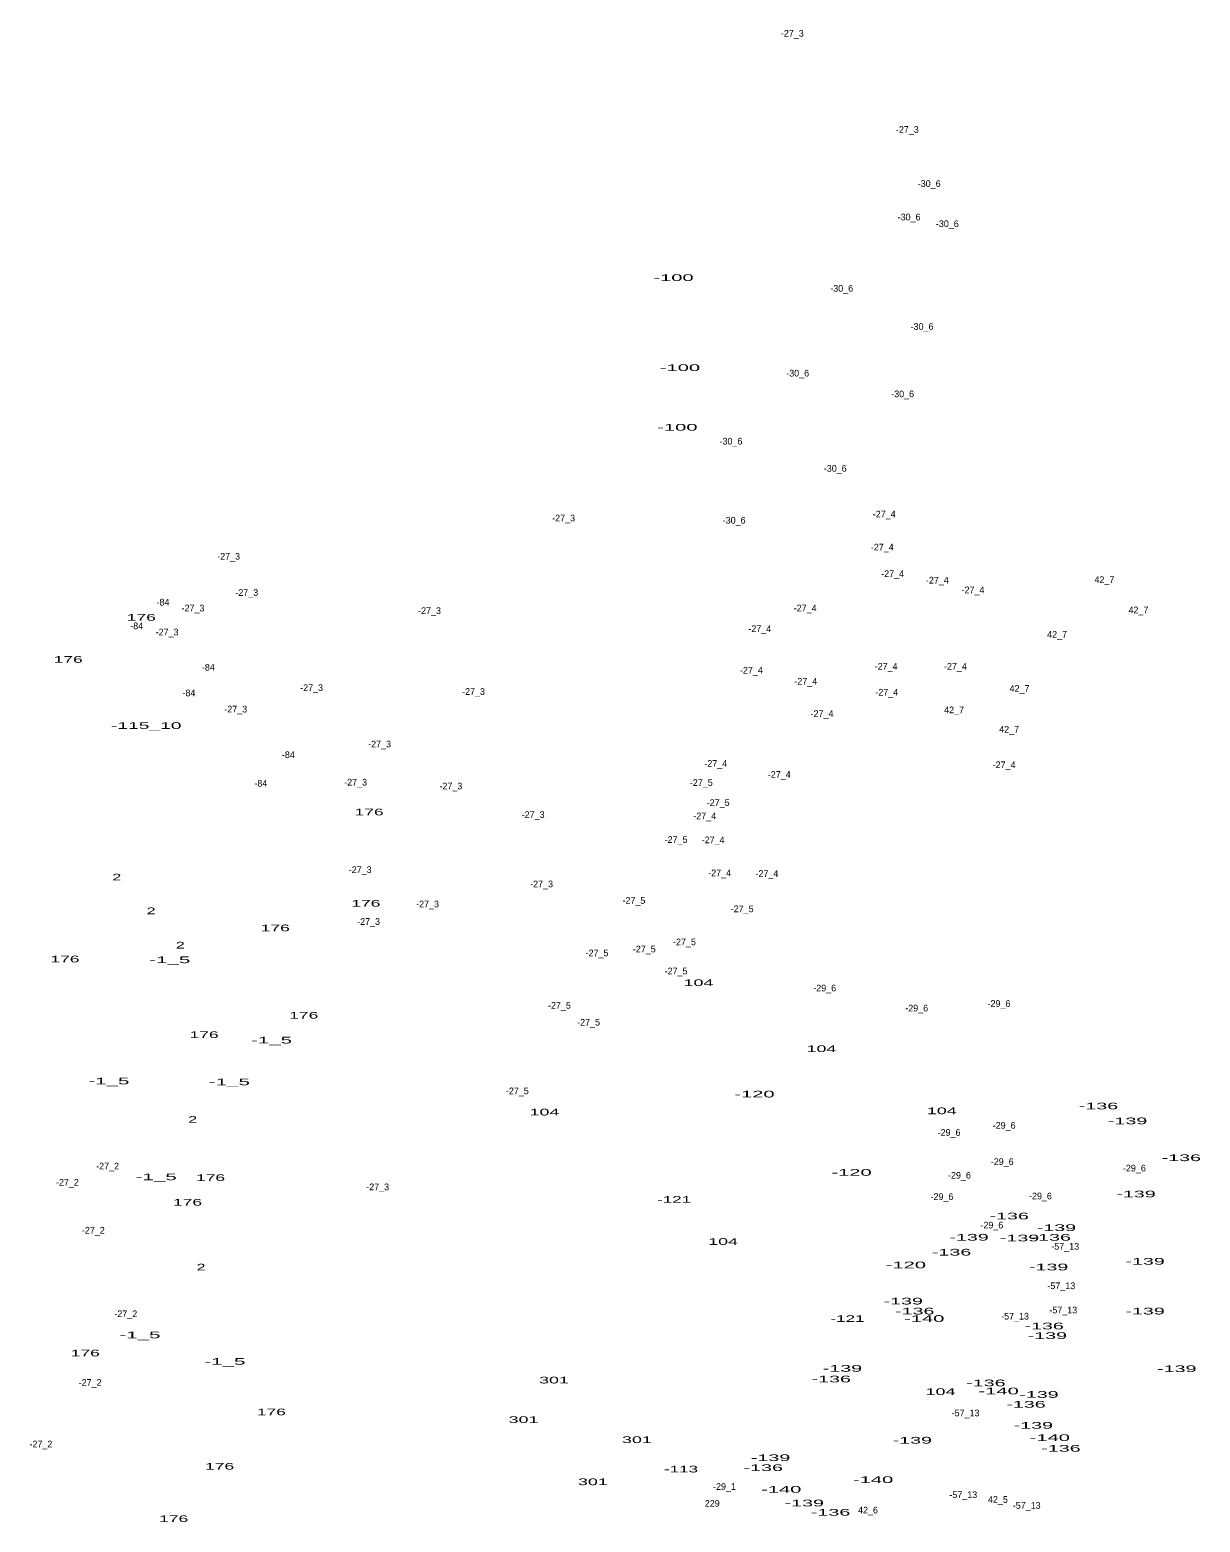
# Model space of a CAD drawing. Extents: x -656096 to -652763, y -1002270 to -998958.
# Drawn here: x -655324 to -654624, y -999851 to -998958 of the extents above; entities that cross this region are included whole.
import ezdxf
from ezdxf.enums import TextEntityAlignment as Align

# ---------------------------------------------------------------- set-up
doc = ezdxf.new("R2010")
doc.units = 0
doc.header["$LTSCALE"] = 1.6
doc.layers.add('24', color=7, linetype='Continuous')

msp = doc.modelspace()

# ---------------------------------------------------------------- texts
at = {"layer": '24'}
for s, p in [('-27_3', (-654867.768, -998961.86)), ('-27_3', (-654798.938, -999019.46)), ('-30_6', (-654785.852, -999051.84)), ('-30_6', (-654797.872, -999071.88)), ('-30_6', (-654775.002, -999075.89)), ('-30_6', (-654838.202, -999114.55)), ('-30_6', (-654790.122, -999137.43)), ('-30_6', (-654864.562, -999165.36)), ('-30_6', (-654801.752, -999177.77)), ('-30_6', (-654904.502, -999206.09)), ('-30_6', (-654842.082, -999222.38)), ('-27_3', (-655004.638, -999252.09)), ('-27_4', (-654812.782, -999249.74)), ('-30_6', (-654902.562, -999253.41)), ('-27_4', (-654813.942, -999269.52)), ('-27_3', (-655205.098, -999274.98)), ('-27_4', (-654807.742, -999285.42)), ('-27_3', (-655194.248, -999296.7)), ('-27_4', (-654780.982, -999289.3)), ('-27_4', (-654759.662, -999295.12)), ('42_7', (-654680.995, -999288.99)), ('-84', (-655244.389, -999302.48)), ('-27_3', (-655226.428, -999306.01)), ('-27_4', (-654860.082, -999305.98)), ('-27_3', (-655084.898, -999307.56)), ('42_7', (-654660.645, -999307.22)), ('-84', (-655260.099, -999316.64)), ('-27_3', (-655241.938, -999320.36)), ('-27_4', (-654887.222, -999318.39)), ('42_7', (-654709.305, -999321.76)), ('-84', (-655217.249, -999341.47)), ('-27_4', (-654811.612, -999340.89)), ('-27_4', (-654770.132, -999340.89)), ('-27_4', (-654892.262, -999343.22)), ('-27_4', (-654859.692, -999349.81)), ('-84', (-655228.879, -999356.79)), ('-27_3', (-655155.468, -999353.71)), ('-27_3', (-655058.538, -999355.96)), ('-27_4', (-654811.232, -999356.4)), ('42_7', (-654731.795, -999354.15)), ('-27_3', (-655200.838, -999366.51)), ('42_7', (-654770.955, -999366.95)), ('-27_4', (-654850.002, -999369.17)), ('42_7', (-654737.995, -999378.59)), ('-84', (-655169.369, -999393.83)), ('-27_3', (-655114.758, -999387.38)), ('-27_4', (-654913.592, -999399.05)), ('-27_4', (-654741.052, -999399.84)), ('-84', (-655185.849, -999410.9)), ('-27_3', (-655129.108, -999410.26)), ('-27_3', (-655072.108, -999412.59)), ('-27_5', (-654922.228, -999410.46)), ('-27_4', (-654875.592, -999405.63)), ('-27_3', (-655022.868, -999429.66)), ('-27_4', (-654920.182, -999430.46)), ('-27_5', (-654912.148, -999422.48)), ('-27_5', (-654937.348, -999444.59)), ('-27_4', (-654915.142, -999444.79)), ('-27_3', (-655126.388, -999462.63)), ('-27_4', (-654911.262, -999464.57)), ('-27_4', (-654882.962, -999464.96)), ('-27_3', (-655017.828, -999471.16)), ('-27_3', (-655086.068, -999483.18)), ('-27_5', (-654962.548, -999481.05)), ('-27_3', (-655121.348, -999493.66)), ('-27_5', (-654897.798, -999486.09)), ('-27_5', (-654956.348, -999510.14)), ('-27_5', (-654932.308, -999505.88)), ('-27_5', (-654984.648, -999512.47)), ('-27_5', (-654937.348, -999523.33)), ('-29_6', (-654848.383, -999533.48)), ('-27_5', (-655007.138, -999543.89)), ('-29_6', (-654793.333, -999545.51)), ('-29_6', (-654744.083, -999542.79)), ('-27_5', (-654989.698, -999553.97)), ('-27_5', (-655032.348, -999595.09)), ('-29_6', (-654740.983, -999615.72)), ('-29_6', (-654773.943, -999619.98)), ('-27_2', (-655277.528, -999640.11)), ('-29_6', (-654742.153, -999637.44)), ('-29_6', (-654663.053, -999641.32)), ('-27_2', (-655301.568, -999649.81)), ('-27_3', (-655115.918, -999652.55)), ('-29_6', (-654767.743, -999645.58)), ('-29_6', (-654778.203, -999658.38)), ('-29_6', (-654719.273, -999657.99)), ('-27_2', (-655286.058, -999678.51)), ('-29_6', (-654748.353, -999675.45)), ('-57_13', (-654704.452, -999688.14)), ('-57_13', (-654706.782, -999711.77)), ('-27_2', (-655266.668, -999728.54)), ('-57_13', (-654734.472, -999729.98)), ('-57_13', (-654705.612, -999726.3)), ('-27_2', (-655287.998, -999769.66)), ('-57_13', (-654764.092, -999787.89)), ('-27_2', (-655317.458, -999806.51)), ('-29_1', (-654908.362, -999831.94)), ('229', (-654915.663, -999842.06)), ('-57_13', (-654765.452, -999836.87)), ('42_5', (-654744.72, -999839.7)), ('42_6', (-654822.484, -999846.09)), ('-57_13', (-654727.502, -999843.26))]:
    msp.add_text(s, height=4, dxfattribs=at).set_placement(p, align=Align.CENTER)
for s, width, p in [('-100', 2.25, (-654938.873, -999108.15)), ('-100', 2.25, (-654935.003, -999162.06)), ('-100', 2.25, (-654936.553, -999197.75)), ('176', 1.95, (-655257.357, -999311.59)), ('176', 1.95, (-655301.117, -999336.77)), ('-115_10', 2.15, (-655254.42, -999376.33)), ('176', 1.95, (-655121.037, -999428.14)), ('2', 1.8, (-655272.041, -999467.11)), ('176', 1.95, (-655122.967, -999482.77)), ('2', 1.8, (-655251.491, -999487.28)), ('176', 1.95, (-655177.187, -999497.49)), ('2', 1.8, (-655234.041, -999507.83)), ('176', 1.95, (-655303.047, -999516.14)), ('-1_5', 2.3, (-655240.321, -999516.6)), ('104', 2, (-654923.919, -999530.31)), ('176', 1.95, (-655160.147, -999549.79)), ('176', 1.95, (-655219.787, -999561.41)), ('-1_5', 2.3, (-655179.451, -999564.7)), ('104', 2, (-654850.339, -999569.83)), ('-1_5', 2.3, (-655276.771, -999589.14)), ('-1_5', 2.3, (-655204.651, -999589.69)), ('-120', 2.25, (-654890.417, -999597.01)), ('104', 2, (-655016.089, -999607.79)), ('104', 2, (-654778.309, -999607.02)), ('-136', 2.2, (-654684.535, -999604.13)), ('2', 1.8, (-655226.671, -999612.17)), ('-139', 2.2, (-654667.115, -999613.04)), ('-136', 2.2, (-654634.965, -999635.12)), ('-120', 2.25, (-654832.327, -999643.89)), ('-1_5', 2.3, (-655248.461, -999646.54)), ('176', 1.95, (-655215.917, -999647.03)), ('176', 1.95, (-655229.707, -999661.79)), ('-121', 1.9, (-654938.517, -999660.1)), ('-139', 2.2, (-654662.075, -999656.82)), ('-136', 2.2, (-654737.985, -999669.99)), ('-139', 2.2, (-654709.715, -999676.97)), ('104', 2, (-654909.199, -999685.27)), ('-139', 2.2, (-654761.995, -999682.71)), ('-139', 2.2, (-654731.785, -999683.16)), ('-136', 2.2, (-654712.805, -999682.77)), ('-136', 2.2, (-654772.445, -999691.66)), ('-139', 2.2, (-654656.655, -999697.11)), ('2', 1.8, (-655221.631, -999700.61)), ('-120', 2.25, (-654799.797, -999699.29)), ('-139', 2.2, (-654714.365, -999700.53)), ('-139', 2.2, (-654801.375, -999720.95)), ('-121', 1.9, (-654834.727, -999731.38)), ('-136', 2.2, (-654794.525, -999726.94)), ('-140', 2.25, (-654788.812, -999731.39)), ('-139', 2.2, (-654656.655, -999726.94)), ('-1_5', 2.3, (-655258.161, -999741.19)), ('-136', 2.2, (-654717.065, -999735.85)), ('-139', 2.2, (-654715.135, -999741.6)), ('176', 1.95, (-655290.887, -999752.05)), ('-1_5', 2.3, (-655207.361, -999757.09)), ('-139', 2.2, (-654837.785, -999761.24)), ('-139', 2.2, (-654637.685, -999761.42)), ('301', 2, (-655010.394, -999768.24)), ('-136', 2.2, (-654844.475, -999767.59)), ('-136', 2.2, (-654751.925, -999769.92)), ('104', 2, (-654779.079, -999775.15)), ('-140', 2.25, (-654744.282, -999774.78)), ('-139', 2.2, (-654720.165, -999776.85)), ('176', 1.95, (-655179.517, -999787.31)), ('-136', 2.2, (-654727.915, -999782.73)), ('301', 2, (-655028.614, -999791.9)), ('-139', 2.2, (-654723.535, -999795.33)), ('301', 2, (-654960.764, -999803.92)), ('-139', 2.2, (-654795.955, -999804.24)), ('-140', 2.25, (-654713.682, -999802.68)), ('-139', 2.2, (-654880.765, -999814.7)), ('-136', 2.2, (-654706.995, -999809.07)), ('176', 1.95, (-655210.497, -999819.85)), ('-113', 1.9, (-654934.347, -999821.53)), ('-136', 2.2, (-654885.145, -999820.67)), ('301', 2, (-654987.124, -999829.14)), ('-140', 2.25, (-654819.412, -999827.86)), ('-140', 2.25, (-654874.402, -999833.67)), ('-139', 2.2, (-654860.635, -999841.82)), ('-136', 2.2, (-654844.865, -999847.4)), ('176', 1.95, (-655237.987, -999851.23))]:
    msp.add_text(s, height=4, dxfattribs=dict(at, width=width)).set_placement(p, align=Align.CENTER)

doc.saveas('drawing.dxf')
